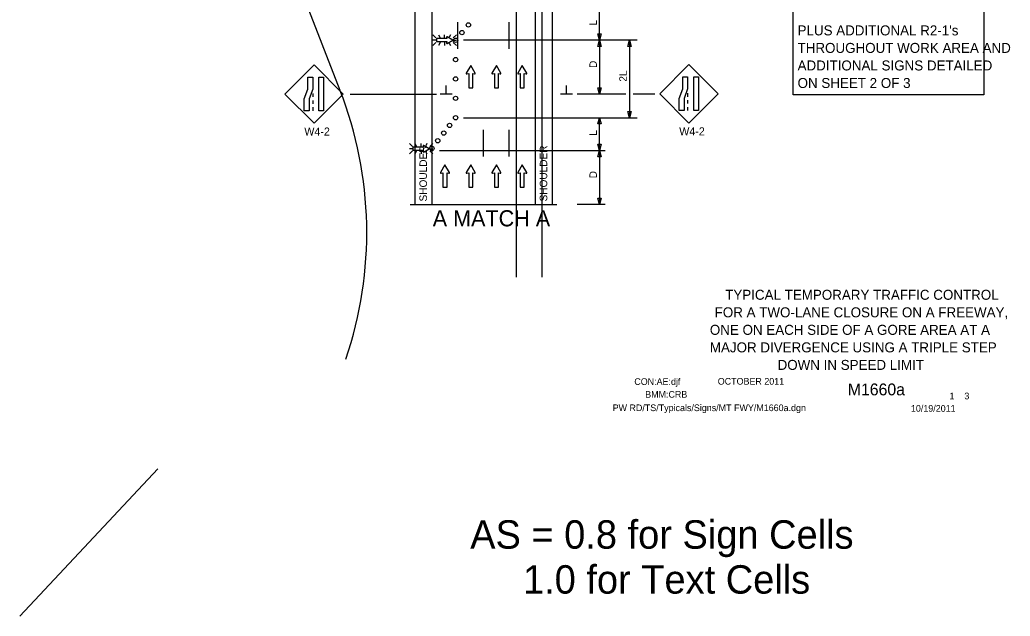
# Model space of a CAD drawing. Extents: x 16519 to 19508, y 5743 to 6974.
# Drawn here: x 16519 to 17440, y 5743 to 6297 of the extents above; entities that cross this region are included whole.
import ezdxf

# ---------------------------------------------------------------- set-up
doc = ezdxf.new("R2010")
doc.units = 0
for name, color, linetype in [('ALI_LEGAL_EX', 7, 'Continuous'), ('BORDER', 7, 'Continuous'), ('BORDER_SIGNAL_WO', 7, 'Continuous'), ('MT_SCRATCH_LEVEL_E', 7, 'Continuous'), ('PAVT_EDGE_EX', 7, 'Continuous'), ('TRAFFIC_SIGNS_PR', 7, 'Continuous'), ('TYPICAL_TEXT_DIMEN_EX', 7, 'Continuous'), ('TYPICAL_TEXT_DIMEN_PR', 7, 'Continuous')]:
    doc.layers.add(name, color=color, linetype=linetype)

msp = doc.modelspace()

# ---------------------------------------------------------------- linework, layer by layer
at = {"layer": 'ALI_LEGAL_EX'}
for p, q in [((16980.68, 6974.12), (16980.68, 6155.98)), ((17004.68, 6974.12), (17004.68, 6155.98)), ((16980.68, 6922.21), (16980.68, 6058.3)), ((17004.68, 6922.21), (17004.68, 6058.3)), ((16594.98, 6800.51), (16817, 6232.14))]:
    msp.add_line(p, q, dxfattribs=at)
for points in [[(16926.45, 6270.33), (16926.45, 6295.33)], [(16974.45, 6270.33), (16974.45, 6295.33)], [(16950.45, 6170.33), (16950.45, 6195.33)], [(16974.45, 6170.33), (16974.45, 6195.33)]]:
    msp.add_lwpolyline(points, dxfattribs=at)
msp.add_arc((16477.95, 6099.7), 364, 341.14594, 21.33672, dxfattribs=at)
at = {"layer": 'BORDER'}
msp.add_line((17289.25, 6011.25), (17289.25, 6011.25), dxfattribs=at)
msp.add_line((17289.25, 6011.25), (17289.25, 6011.25), dxfattribs=at)
at = {"layer": 'MT_SCRATCH_LEVEL_E'}
for p, q in [((16938.54, 6255.03), (16934.43, 6247.79)), ((16942.69, 6247.79), (16938.54, 6255.03)), ((16962.45, 6255.03), (16958.33, 6247.79)), ((16966.59, 6247.79), (16962.45, 6255.03)), ((16986.5, 6255.03), (16982.39, 6247.79)), ((16990.65, 6247.79), (16986.5, 6255.03)), ((16934.91, 6247.11), (16936.69, 6247.43)), ((16936.69, 6247.43), (16936.69, 6234.17)), ((16940.43, 6234.17), (16940.43, 6247.43)), ((16940.43, 6247.43), (16942.21, 6247.11)), ((16958.82, 6247.11), (16960.59, 6247.43)), ((16960.59, 6247.43), (16960.59, 6234.17)), ((16964.34, 6234.17), (16964.34, 6247.43)), ((16964.34, 6247.43), (16966.11, 6247.11)), ((16982.87, 6247.11), (16984.65, 6247.43)), ((16984.65, 6247.43), (16984.65, 6234.17)), ((16988.39, 6234.17), (16988.39, 6247.43)), ((16988.39, 6247.43), (16990.17, 6247.11)), ((16936.69, 6234.17), (16940.43, 6234.17)), ((16960.59, 6234.17), (16964.34, 6234.17)), ((16984.65, 6234.17), (16988.39, 6234.17)), ((16914.64, 6162.72), (16910.53, 6155.48)), ((16918.78, 6155.48), (16914.64, 6162.72)), ((16938.54, 6162.72), (16934.43, 6155.48)), ((16942.69, 6155.48), (16938.54, 6162.72)), ((16962.45, 6162.72), (16958.33, 6155.48)), ((16966.59, 6155.48), (16962.45, 6162.72)), ((16986.5, 6162.72), (16982.39, 6155.48)), ((16990.65, 6155.48), (16986.5, 6162.72)), ((16911.01, 6154.79), (16912.79, 6155.11)), ((16912.79, 6155.11), (16912.79, 6141.85)), ((16916.53, 6141.85), (16916.53, 6155.11)), ((16916.53, 6155.11), (16918.31, 6154.79)), ((16934.91, 6154.79), (16936.69, 6155.11)), ((16936.69, 6155.11), (16936.69, 6141.85)), ((16940.43, 6141.85), (16940.43, 6155.11)), ((16940.43, 6155.11), (16942.21, 6154.79)), ((16958.82, 6154.79), (16960.59, 6155.11)), ((16960.59, 6155.11), (16960.59, 6141.85)), ((16964.34, 6141.85), (16964.34, 6155.11)), ((16964.34, 6155.11), (16966.11, 6154.79)), ((16982.87, 6154.79), (16984.65, 6155.11)), ((16984.65, 6155.11), (16984.65, 6141.85)), ((16988.39, 6141.85), (16988.39, 6155.11)), ((16988.39, 6155.11), (16990.17, 6154.79)), ((16912.79, 6141.85), (16916.53, 6141.85)), ((16936.69, 6141.85), (16940.43, 6141.85)), ((16960.59, 6141.85), (16964.34, 6141.85)), ((16984.65, 6141.85), (16988.39, 6141.85))]:
    msp.add_line(p, q, dxfattribs=at)
for centre, start, end in [((16934.84, 6247.57), 150.42484, 279.96381), ((16942.28, 6247.57), 260.03619, 29.77312), ((16958.74, 6247.57), 150.42484, 279.96381), ((16966.18, 6247.57), 260.03619, 29.77312), ((16982.8, 6247.57), 150.42484, 279.96381), ((16990.24, 6247.57), 260.03619, 29.77312), ((16910.93, 6155.25), 150.42484, 279.96381), ((16918.38, 6155.25), 260.03619, 29.77312), ((16934.84, 6155.25), 150.42484, 279.96381), ((16942.28, 6155.25), 260.03619, 29.77312), ((16958.74, 6155.25), 150.42484, 279.96381), ((16966.18, 6155.25), 260.03619, 29.77312), ((16982.8, 6155.25), 150.42484, 279.96381), ((16990.24, 6155.25), 260.03619, 29.77312)]:
    msp.add_arc(centre, 0.463, start, end, dxfattribs=at)
at = {"layer": 'PAVT_EDGE_EX'}
for p, q in [((16886.45, 6480.53), (16886.45, 6125.9)), ((16902.45, 6480.53), (16902.45, 6125.9)), ((16998.45, 6480.53), (16998.45, 6125.9)), ((17014.45, 6480.53), (17014.45, 6125.9))]:
    msp.add_line(p, q, dxfattribs=at)
at = {"layer": 'TRAFFIC_SIGNS_PR'}
for p, q in [((16906.22, 6280.57), (16903.4, 6283.39)), ((16908.52, 6283.39), (16910.15, 6280.57)), ((16914.31, 6280.57), (16914.31, 6283.39)), ((16919.78, 6283.39), (16918.57, 6281.3)), ((16925.21, 6283.39), (16922.39, 6280.57)), ((16906.22, 6278.54), (16903.4, 6278.54)), ((16906.22, 6276.51), (16903.4, 6273.69)), ((16910.17, 6276.51), (16908.54, 6273.69)), ((16914.31, 6276.51), (16914.31, 6273.69)), ((16918.49, 6275.87), (16919.75, 6273.69)), ((16922.39, 6278.54), (16925.21, 6278.54)), ((16925.21, 6273.69), (16922.39, 6276.51)), ((16792.88, 6255.63), (16765.72, 6228.48)), ((16820.03, 6228.48), (16792.88, 6255.63)), ((17141.5, 6255.78), (17114.35, 6228.63)), ((17168.65, 6228.63), (17141.5, 6255.78)), ((16765.72, 6228.48), (16792.88, 6201.33)), ((16791.63, 6228.97), (16791.63, 6225.77)), ((16792.88, 6201.33), (16820.03, 6228.48)), ((17114.35, 6228.63), (17141.5, 6201.47)), ((17140.25, 6229.12), (17140.25, 6225.92)), ((17141.5, 6201.47), (17168.65, 6228.63)), ((16791.63, 6222.57), (16791.63, 6219.37)), ((17140.25, 6222.72), (17140.25, 6219.52)), ((17140.25, 6216.32), (17140.25, 6213.12)), ((16791.63, 6216.17), (16791.63, 6212.97)), ((16884.35, 6179.62), (16881.53, 6182.44)), ((16886.65, 6182.44), (16888.27, 6179.62)), ((16892.43, 6179.62), (16892.43, 6182.44)), ((16897.9, 6182.44), (16896.69, 6180.35)), ((16903.34, 6182.44), (16900.52, 6179.62)), ((16884.35, 6177.59), (16881.53, 6177.59)), ((16884.35, 6175.56), (16881.53, 6172.74)), ((16888.3, 6175.56), (16886.67, 6172.74)), ((16892.43, 6175.56), (16892.43, 6172.74)), ((16896.62, 6174.92), (16897.88, 6172.74)), ((16900.52, 6177.59), (16903.34, 6177.59)), ((16903.34, 6172.74), (16900.52, 6175.56))]:
    msp.add_line(p, q, dxfattribs=at)
for points in [[(16916.13, 6281.22), (16916.36, 6279.93), (16906.64, 6279.93), (16906.64, 6277.18), (16916.36, 6277.18), (16916.13, 6275.88)], [(16916.63, 6275.53), (16921.94, 6278.54), (16916.63, 6281.58)], [(16894.26, 6180.27), (16894.49, 6178.97), (16884.77, 6178.97), (16884.77, 6176.23), (16894.49, 6176.23), (16894.26, 6174.93)], [(16894.76, 6174.57), (16900.07, 6177.59), (16894.76, 6180.63)]]:
    msp.add_lwpolyline(points, dxfattribs=at)
for points in [[(16791.63, 6244.22), (16791.63, 6233.04), (16788.29, 6224.15), (16788.29, 6212.97), (16783.79, 6212.97), (16783.79, 6224.15), (16787.14, 6233.04), (16787.14, 6244.22)], [(16801.77, 6244.22), (16801.77, 6212.97), (16797.27, 6212.97), (16797.27, 6244.22)], [(17140.25, 6244.36), (17140.25, 6233.18), (17136.91, 6224.3), (17136.91, 6213.12), (17132.42, 6213.12), (17132.42, 6224.3), (17135.76, 6233.18), (17135.76, 6244.36)], [(17150.39, 6244.36), (17150.39, 6213.12), (17145.9, 6213.12), (17145.9, 6244.36)]]:
    msp.add_lwpolyline(points, close=True, dxfattribs=at)
for centre in [(16936.44, 6292.75), (16930.44, 6285.61), (16924.44, 6278.47), (16924.44, 6260.47), (16924.44, 6242.47), (16924.44, 6224.47), (16924.44, 6206.47), (16918.95, 6199.34), (16913.45, 6192.21), (16902.46, 6177.96), (16907.95, 6185.08)]:
    msp.add_circle(centre, 2, dxfattribs=at)
for centre, start, end in [((16916.47, 6281.28), 61.48329, 189.95933), ((16916.47, 6275.82), 170.73078, 298.89165), ((16894.6, 6180.33), 61.48329, 189.95933), ((16894.6, 6174.87), 170.73078, 298.89165)]:
    msp.add_arc(centre, 0.341, start, end, dxfattribs=at)
at = {"layer": 'TYPICAL_TEXT_DIMEN_EX'}
msp.add_lwpolyline([(17238.46, 6313.09), (17415.73, 6313.09), (17415.73, 6227.77), (17238.46, 6227.77)], close=True, dxfattribs=at)
at = {"layer": 'TYPICAL_TEXT_DIMEN_PR'}
for p, q in [((17058.45, 6278.47), (17058.45, 6307.03)), ((17058.45, 6278.47), (17056.88, 6284.33)), ((17056.88, 6284.33), (17058.45, 6284.33)), ((17058.45, 6284.33), (17060.02, 6284.33)), ((17060.02, 6284.33), (17058.45, 6278.47)), ((17093.24, 6278.47), (16931.95, 6278.47)), ((17056.88, 6272.61), (17058.45, 6278.47)), ((17058.45, 6272.61), (17056.88, 6272.61)), ((17058.45, 6278.47), (17058.45, 6228.47)), ((17058.45, 6278.47), (17060.02, 6272.61)), ((17060.02, 6272.61), (17058.45, 6272.61)), ((17084.68, 6272.61), (17086.25, 6278.47)), ((17086.25, 6272.61), (17084.68, 6272.61)), ((17086.25, 6278.47), (17087.82, 6272.61)), ((17086.25, 6278.47), (17086.25, 6206.47)), ((17087.82, 6272.61), (17086.25, 6272.61)), ((16915.73, 6228.47), (16915.73, 6236.25)), ((17027.57, 6228.47), (17027.57, 6236.25)), ((16826.44, 6228.47), (16906.74, 6228.47)), ((16921.36, 6228.47), (16910.11, 6228.47)), ((17033.2, 6228.47), (17021.95, 6228.47)), ((17082.83, 6228.47), (17037.45, 6228.47)), ((17058.45, 6228.47), (17056.88, 6234.33)), ((17056.88, 6234.33), (17058.45, 6234.33)), ((17058.45, 6234.33), (17060.02, 6234.33)), ((17060.02, 6234.33), (17058.45, 6228.47)), ((17109.92, 6228.47), (17089.54, 6228.47)), ((17086.25, 6206.47), (17084.68, 6212.33)), ((17084.68, 6212.33), (17086.25, 6212.33)), ((17086.25, 6212.33), (17087.82, 6212.33)), ((17087.82, 6212.33), (17086.25, 6206.47)), ((16931.95, 6206.47), (17093.24, 6206.47)), ((17056.88, 6200.61), (17058.45, 6206.47)), ((17058.45, 6200.61), (17056.88, 6200.61)), ((17058.45, 6175.9), (17058.45, 6206.47)), ((17058.45, 6206.47), (17060.02, 6200.61)), ((17060.02, 6200.61), (17058.45, 6200.61)), ((17058.45, 6175.9), (17056.88, 6181.77)), ((17056.88, 6181.77), (17058.45, 6181.77)), ((17058.45, 6181.77), (17060.02, 6181.77)), ((17060.02, 6181.77), (17058.45, 6175.9)), ((16909.4, 6175.9), (17063.45, 6175.9)), ((17056.88, 6170.04), (17058.45, 6175.9)), ((17058.45, 6175.9), (17058.45, 6125.9)), ((17058.45, 6175.9), (17060.02, 6170.04)), ((17058.45, 6170.04), (17056.88, 6170.04)), ((17060.02, 6170.04), (17058.45, 6170.04)), ((16882.15, 6125.9), (17018.8, 6125.9)), ((17063.45, 6125.9), (17037.45, 6125.9)), ((17058.45, 6125.9), (17056.88, 6131.77)), ((17056.88, 6131.77), (17058.45, 6131.77)), ((17058.45, 6131.77), (17060.02, 6131.77)), ((17060.02, 6131.77), (17058.45, 6125.9)), ((16647.75, 5880), (16519.28, 5743.1))]:
    msp.add_line(p, q, dxfattribs=at)

# ---------------------------------------------------------------- texts
at = {"layer": 'BORDER'}
for s, p in [('TYPICAL TEMPORARY TRAFFIC CONTROL', (17175.21, 6037.21)), ('FOR A TWO-LANE CLOSURE ON A FREEWAY,', (17165.41, 6020.91)), ('ONE ON EACH SIDE OF A GORE AREA AT A ', (17160.92, 6004.62)), ('MAJOR DIVERGENCE USING A TRIPLE STEP ', (17160.92, 5988.32)), ('DOWN IN SPEED LIMIT', (17223.92, 5972.02))]:
    msp.add_text(s, height=9.3, dxfattribs=at).set_placement(p)
at = {"layer": 'BORDER_SIGNAL_WO'}
for s, height, p in [('CON:AE:djf  ', 6.2, (17090.69, 5958.06)), ('    OCTOBER 2011    ', 6.2, (17159.08, 5958.34)), ('    M1660a   ', 11, (17272.86, 5948.38)), ('BMM:CRB   ', 6.2, (17100.81, 5946.17)), (' 1    3 ', 6.2, (17381.45, 5944.7)), ('PW RD/TS/Typicals/Signs/MT FWY/M1660a.dgn      ', 6.2, (17070.55, 5933.71)), ('10/19/2011    ', 6.2, (17347.93, 5933.13)), ('AS = 0.8 for Sign Cells', 26.4241, (16938.08, 5805.84)), ('     1.0 for Text Cells', 26.4241, (16938.08, 5764.05))]:
    msp.add_text(s, height=height, dxfattribs=at).set_placement(p)
at = {"layer": 'TRAFFIC_SIGNS_PR'}
for p in [(16783.84, 6189.89), (17132.46, 6190.03)]:
    msp.add_text('W4-2', height=7.44, dxfattribs=at).set_placement(p)
at = {"layer": 'TYPICAL_TEXT_DIMEN_EX'}
for s, p in [("PLUS ADDITIONAL R2-1's", (17242.51, 6282.97)), ('THROUGHOUT WORK AREA AND', (17242.51, 6266.67)), ('ADDITIONAL SIGNS DETAILED', (17242.51, 6250.37)), ('ON SHEET 2 OF 3', (17242.51, 6234.07))]:
    msp.add_text(s, height=9.3, dxfattribs=at).set_placement(p)
at = {"layer": 'TYPICAL_TEXT_DIMEN_PR'}
for s, p in [('L', (17055.98, 6292.11)), ('D', (17055.89, 6252.69)), ('2L', (17083.69, 6239.97)), ('L', (17055.89, 6189.76)), ('SHOULDER', (16897.88, 6128.61)), ('SHOULDER', (17009.74, 6128.61)), ('D', (17055.89, 6150.12))]:
    msp.add_text(s, height=7, rotation=90, dxfattribs=at).set_placement(p)
msp.add_text('A MATCH A', height=15, dxfattribs=at).set_placement((16903.24, 6105.44))

doc.saveas('drawing.dxf')
